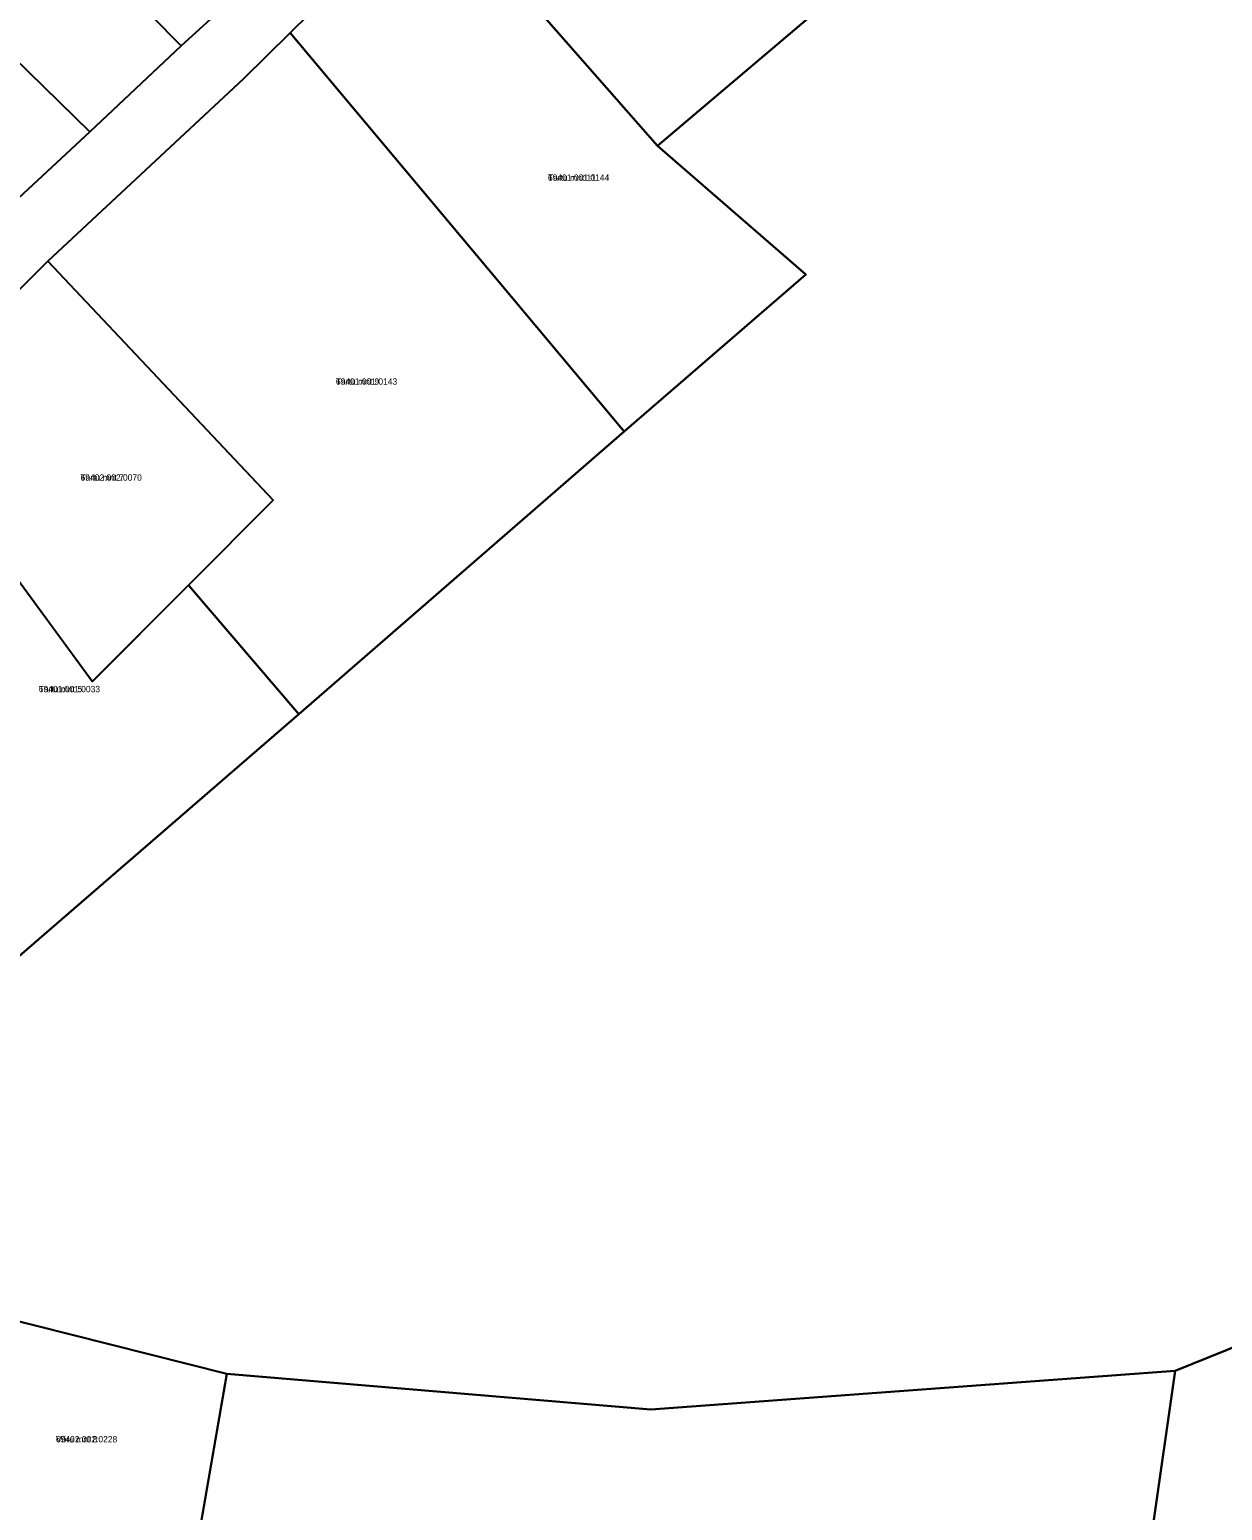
# Model space of a CAD drawing. Extents: x 621116 to 647354, y 6433782 to 6479868.
# Drawn here: x 632584.2 to 632866.4, y 6446793.4 to 6447143.7 of the extents above; entities that cross this region are included whole.
import ezdxf

# ---------------------------------------------------------------- set-up
doc = ezdxf.new("R2010")
doc.units = 0
for name, color, linetype in [('L_AADRESS', 7, 'Continuous'), ('PIIR', 7, 'Continuous'), ('TUNNUS', 7, 'Continuous')]:
    doc.layers.add(name, color=color, linetype=linetype)

msp = doc.modelspace()

# ---------------------------------------------------------------- linework, layer by layer
at = {"layer": 'PIIR'}
for points in [[(632883.55, 6447433.55), (632823.56, 6447364.54), (632765.83, 6447294.39), (632710.64, 6447218.39), (632706.33, 6447212.09), (632679.44, 6447177.2), (632680.2, 6447176.14), (632678.45, 6447175.07), (632645.86, 6447142.95), (632634.81, 6447132.1), (632588.47, 6447088.99), (632550.7, 6447051.42), (632511.3, 6447010.02), (632486.88, 6446984.32), (632455.65, 6446950.25), (632411.59, 6446899.66), (632377.44, 6446852.14), (632370.98, 6446831.17), (632362.97, 6446826.87), (632358.02, 6446811.05), (632347.63, 6446778.24)], [(633018.53, 6446892.34), (632855.22, 6446826.42), (632731.22, 6446817.27), (632630.88, 6446825.72), (632557.57, 6446844.2), (632560.82, 6446866.69), (632549.2, 6446939.86), (632558.62, 6446949.17), (632579.41, 6446922.53), (632647.93, 6446981.82), (632724.87, 6447048.64), (632767.82, 6447085.82), (632732.74, 6447116.24), (632780.64, 6447156.88), (632786.41, 6447163.78), (632792.83, 6447158.42), (632824.27, 6447148.02), (632854.81, 6447243.77), (632865.67, 6447258.13), (632870.09, 6447255.09)], [(632329.9, 6446773.82), (632340.08, 6446815.51), (632340.23, 6446818.86), (632339.46, 6446821.58), (632340.12, 6446849.46), (632345.88, 6446856.63), (632354.81, 6446860.66), (632389.48, 6446904.16), (632394.54, 6446901.51), (632425.68, 6446938.69), (632435.55, 6446947.84), (632448.65, 6446962.5), (632453.23, 6446967.82), (632480.34, 6446998.92), (632508.01, 6447030.37), (632530.09, 6447055.45), (632545.41, 6447071.48), (632554.37, 6447078.44), (632556.25, 6447080.21), (632575.88, 6447098.64), (632598.45, 6447119.53), (632620.08, 6447139.91), (632643.5, 6447161.29)], [(633423.9, 6446244.22), (633345.99, 6446444.44), (633336.77, 6446466.81), (633277.73, 6446520.44), (633253.66, 6446542.18), (633192.48, 6446624.48), (633146.73, 6446717.51), (633046.98, 6446658.66), (633029.94, 6446647.53), (633030.82, 6446657.61), (633034.45, 6446717.16), (632952.84, 6446731.25), (632844.35, 6446750.42), (632855.22, 6446826.42), (633018.53, 6446892.34), (633220.49, 6446953.77), (633273.59, 6446807.17), (633275.15, 6446795.73), (633456.46, 6446381.69)]]:
    msp.add_lwpolyline(points, dxfattribs=at)
for points in [[(632706.33, 6447212.09), (632780.64, 6447156.88), (632732.74, 6447116.24), (632680.2, 6447176.14), (632679.44, 6447177.2)], [(632620.08, 6447139.91), (632584.6, 6447175.85), (632593.65, 6447184.65), (632602, 6447192.72), (632609.25, 6447185.19), (632614.84, 6447190.06), (632643.5, 6447161.29)], [(632695.31, 6447083.99), (632645.86, 6447142.95), (632678.45, 6447175.07), (632680.2, 6447176.14), (632732.74, 6447116.24), (632767.82, 6447085.82), (632724.87, 6447048.64)], [(632598.45, 6447119.53), (632562.08, 6447155.09), (632584.6, 6447175.85), (632620.08, 6447139.91)], [(632598.45, 6447119.53), (632575.88, 6447098.64), (632540.32, 6447135.02), (632562.08, 6447155.09)], [(632641.79, 6447032.42), (632588.47, 6447088.99), (632634.81, 6447132.1), (632645.86, 6447142.95), (632695.31, 6447083.99), (632724.87, 6447048.64), (632647.93, 6446981.82), (632621.77, 6447012.3)], [(632550.7, 6447051.42), (632588.47, 6447088.99), (632641.79, 6447032.42), (632621.77, 6447012.3), (632598.99, 6446989.55), (632569.7, 6447029.45)], [(632558.62, 6446949.17), (632511.3, 6447010.02), (632550.7, 6447051.42), (632569.7, 6447029.45), (632599.07, 6446989.55), (632621.77, 6447012.3), (632647.93, 6446981.82), (632579.41, 6446922.53)], [(632550.69, 6446794.14), (632557.57, 6446844.2), (632630.88, 6446825.72), (632622.04, 6446774.77)], [(632855.22, 6446826.42), (632844.35, 6446750.42), (632831.82, 6446752.73), (632768.06, 6446734.64), (632754.49, 6446740.45), (632738.21, 6446746.59), (632713.89, 6446754.71), (632689.74, 6446762.06), (632623.29, 6446781.93), (632630.88, 6446825.72), (632731.22, 6446817.27)]]:
    msp.add_lwpolyline(points, close=True, dxfattribs=at)

# ---------------------------------------------------------------- texts
at = {"layer": 'L_AADRESS'}
for s, p in [('Tartu mnt 11', (632706.84, 6447107.98)), ('Tartu mnt 9', (632656.67, 6447059.74)), ('Tartu mnt 7', (632596.25, 6447037.02)), ('Tartu mnt 5', (632586.36, 6446986.98)), ('Võru mnt 8', (632590.43, 6446809.49))]:
    msp.add_text(s, height=1.5, dxfattribs=at).set_placement(p)
at = {"layer": 'TUNNUS'}
for s, p in [('69401:001:0144', (632706.84, 6447107.98)), ('69401:001:0143', (632656.67, 6447059.74)), ('69402:002:0070', (632596.25, 6447037.02)), ('69401:001:0033', (632586.36, 6446986.98)), ('69402:002:0228', (632590.43, 6446809.49))]:
    msp.add_text(s, height=1.5, dxfattribs=at).set_placement(p)

doc.saveas('drawing.dxf')
